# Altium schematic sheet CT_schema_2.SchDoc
size 395 x 205 mm
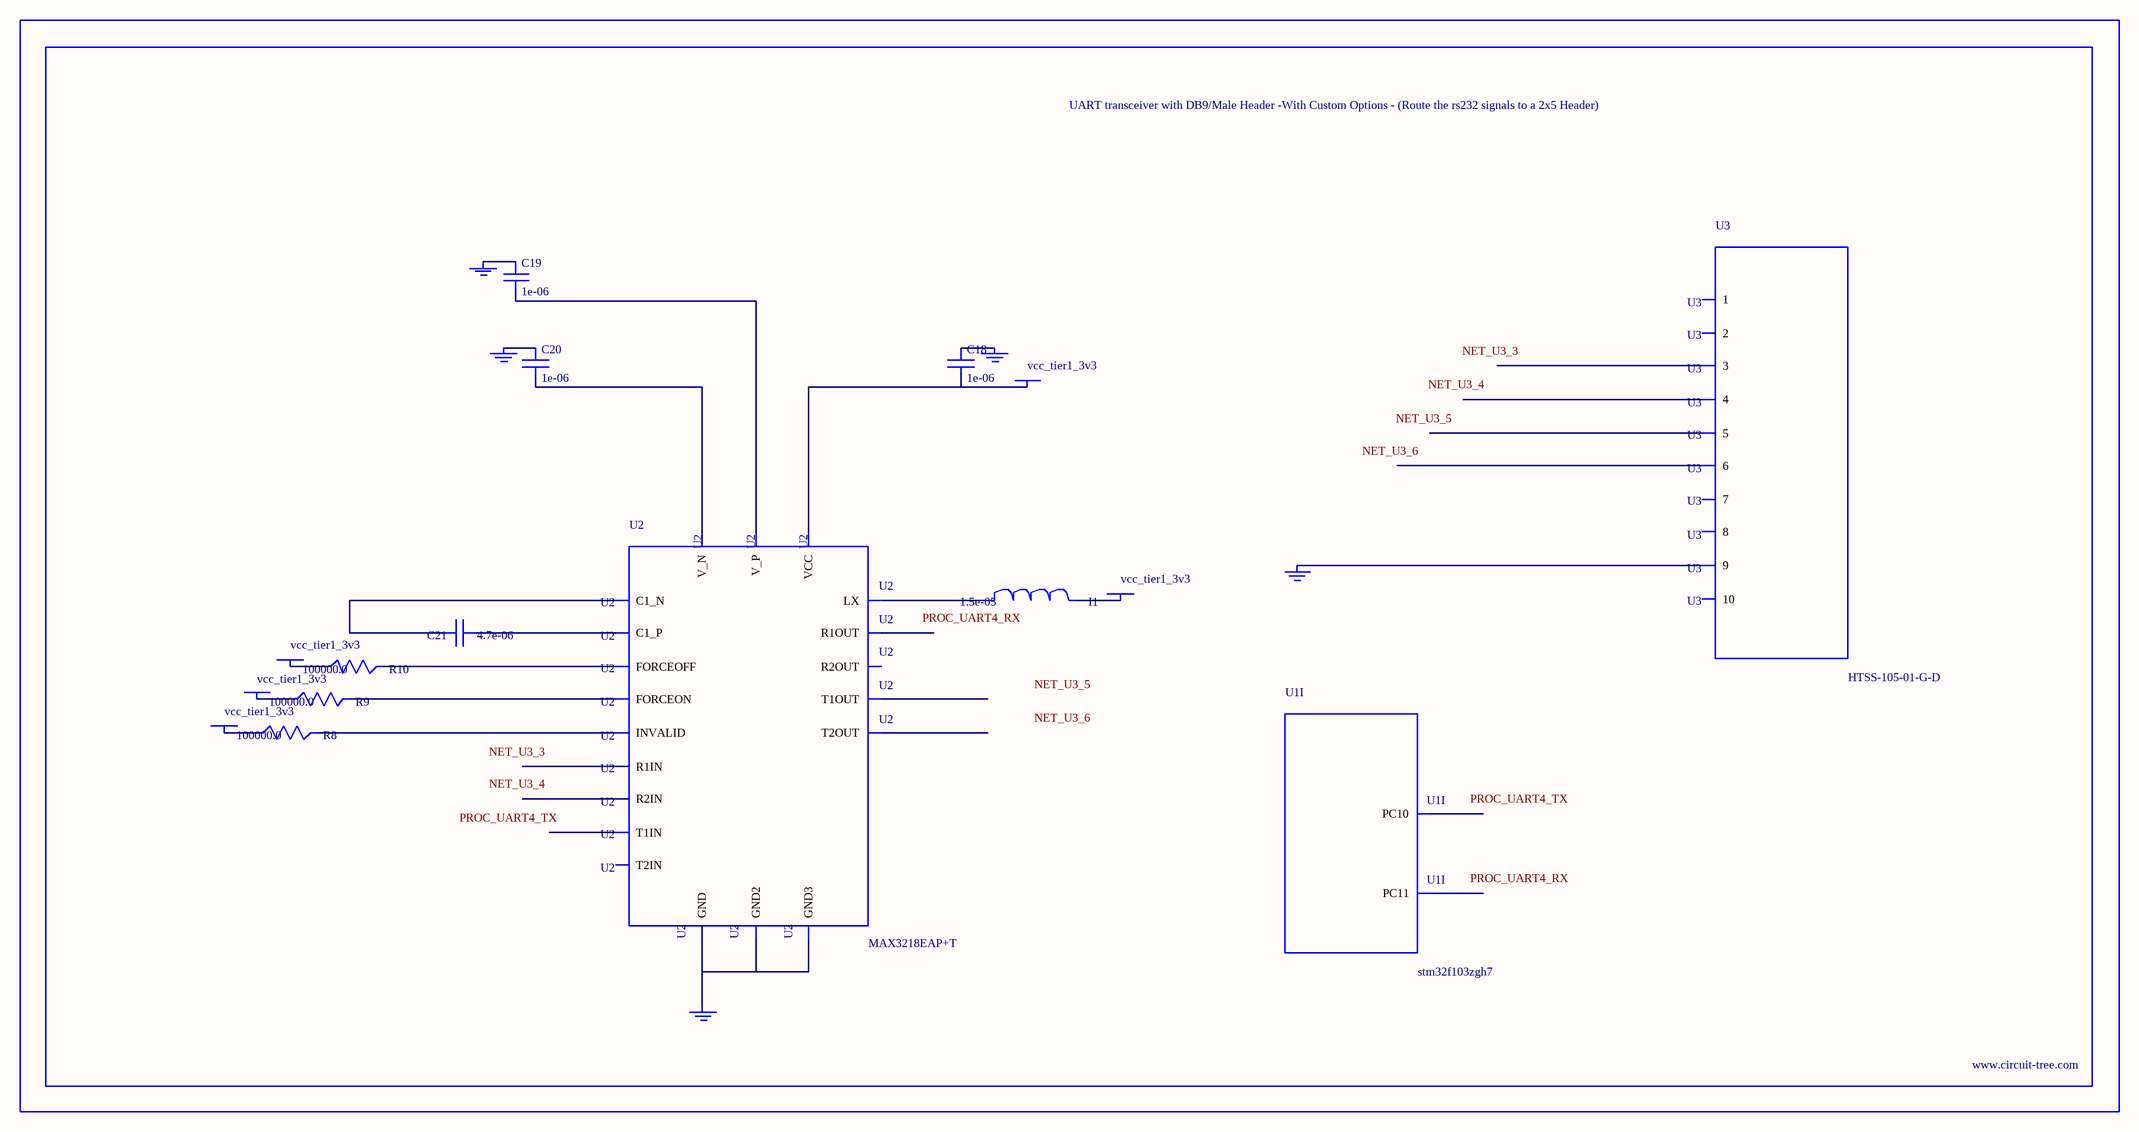
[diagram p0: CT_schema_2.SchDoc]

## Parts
BORDER1  (no value)
C18  1e-06  [C0603]
C19  1e-06  [C0603]
C20  1e-06  [C0603]
C21  4.7e-06  [C0805]
GND_INSTANCE_1_0  (no value)
GND_INSTANCE_1_1  (no value)
GND_INSTANCE_1_2  (no value)
GND_INSTANCE_1_3  (no value)
GND_INSTANCE_1_4  (no value)
I1  1.5e-05  [L1210]
POWER_INSTANCE_1_0  vcc_tier1_3v3
POWER_INSTANCE_1_1  vcc_tier1_3v3
POWER_INSTANCE_1_2  vcc_tier1_3v3
POWER_INSTANCE_1_3  vcc_tier1_3v3
POWER_INSTANCE_1_4  vcc_tier1_3v3
R8  100000.0  [R0603]
R9  100000.0  [R0603]
R10  100000.0  [R0603]
U1  stm32f103zgh7  [LFBGA144]  (part I of 12)
U2  MAX3218EAP+T  [SSOP-20]
U3  HTSS-105-01-G-D  [HTSS-105-01-G-D]

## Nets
NetC18_1: C18.1 GND_INSTANCE_1_0.0(GND)
NetC18_2: C18.2 POWER_INSTANCE_1_4.0(PWR) U2.6(VCC)
NetC19_1: C19.1 GND_INSTANCE_1_2.0(GND)
NetC19_2: C19.2 U2.19(V_P)
NetC20_1: C20.1 GND_INSTANCE_1_1.0(GND)
NetC20_2: C20.2 U2.15(V_N)
NetC21_1: C21.1 U2.18(C1_P)
NetC21_2: C21.2 U2.16(C1_N)
NetGND_INSTANCE_1_3_0: GND_INSTANCE_1_3.0(GND) U2.5(GND) U2.17(GND2) U2.20(GND3)
NetGND_INSTANCE_1_4_0: GND_INSTANCE_1_4.0(GND) U3.9
NetI1_1: I1.1 U2.1(LX)
NetI1_2: I1.2 POWER_INSTANCE_1_0.0(PWR)
NetPOWER_INSTANCE_1_1_0: POWER_INSTANCE_1_1.0(PWR) R8.1
NetPOWER_INSTANCE_1_2_0: POWER_INSTANCE_1_2.0(PWR) R9.1
NetPOWER_INSTANCE_1_3_0: POWER_INSTANCE_1_3.0(PWR) R10.1
NetR8_2: R8.2 U2.2(INVALID)
NetR9_2: R9.2 U2.3(FORCEON)
NetR10_2: R10.2 U2.4(FORCEOFF)

Not connected (* = marked no-connect by the designer): U1 B10(PC11) B11(PC10); U2 7(T1IN) 8(T2IN) 9(R1OUT) 10(R2OUT) 11(R2IN) 12(R1IN) 13(T2OUT) 14(T1OUT); U3 1 2 3 4 5 6 7 8 10

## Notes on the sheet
- Labels drawn without touching a wire or pin: NET_U3_3, NET_U3_4, NET_U3_5, NET_U3_6, PROC_UART4_RX, PROC_UART4_TX

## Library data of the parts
BORDER1 = BORDER_PAGE1
C18-C20 = C0603C105K3RACTU
C21 = C0805C475K4RACTU
GND_INSTANCE_1_0-GND_INSTANCE_1_4 = GND
I1 = L1210R150MDWIT
POWER_INSTANCE_1_0-POWER_INSTANCE_1_4 = PWR
R8-R10 = RC0603JR-07100KL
